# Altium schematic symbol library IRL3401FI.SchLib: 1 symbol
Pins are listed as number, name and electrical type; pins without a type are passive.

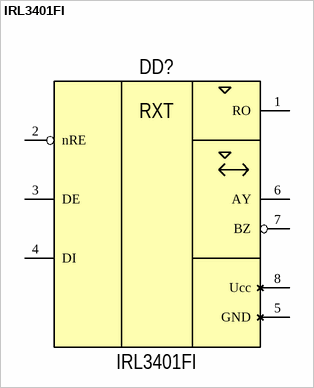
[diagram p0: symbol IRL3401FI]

## IRL3401FI
designator DD?
Микросхема приемопередатчика по стандарту RS-485/422; TemperatureOperating: - 40°C to + 85°C
pins: 1 RO, 2 nRE, 3 DE, 4 DI, 5 GND, 6 AY, 7 BZ, 8 Ucc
